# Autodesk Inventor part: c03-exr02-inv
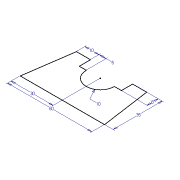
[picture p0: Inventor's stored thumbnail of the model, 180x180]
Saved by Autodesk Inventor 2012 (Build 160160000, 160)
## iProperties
Shininess: 64.0
Length Units: 11269
Angle Units: 11279
Time Units: 11290
Mass Units: 11283
Length Display Precision: 3
Angle Display Precision: 2
Compacted: True
Created: 2002-02
Part Number: c03-exr02-inv
Document SubType Name: Modeling
Density: 1 g/cm^3
Material: Default
Density: 0.0
Volumn: 0.0
Area: 0.0
PropertySet Name: Model Information
Control State: 0
Master: False
Checked Out: False
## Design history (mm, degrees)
sketch "Sketch1"
  geometry: L1 (-34.071, -15.784)-(25.929, -15.784); L2 (25.929, -15.784)-(20.929, 19.216); L3 (20.929, 19.216)-(10.929, 19.216); L4 (10.929, 19.216)-(10.929, 11.216); L5 (10.929, 11.216)-(5.929, 11.216); L6 (-14.071, 11.216)-(-19.071, 11.216); L7 (-19.071, 11.216)-(-19.071, 19.216); L8 (-19.071, 19.216)-(-29.071, 19.216); L9 (-29.071, 19.216)-(-34.071, -15.784); A1 r 10 centre (-4.071, 11.216) between (-14.071, 11.216) and (5.929, 11.216)
  constraints: 18 end point, 5 parallel, 4 equal length, 2 point on circle, 1 centre point, 1 horizontal, 1 perpendicular, 1 point on line
  dimensions: "d0" = 60 distance of L1.start L1.end; "d1" = 10 radius of A1; "d2" = 10 distance of L7.end L8.end; "d3" = 5 distance of L6.start L6.end; "d4" = 8 distance of L3.end L4.end; "d5" = 35 distance between parallel lines of L1 L3; "d6" = 30 horizontal distance of L1.start A1.centre
